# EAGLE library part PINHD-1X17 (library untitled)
PIN HEADER
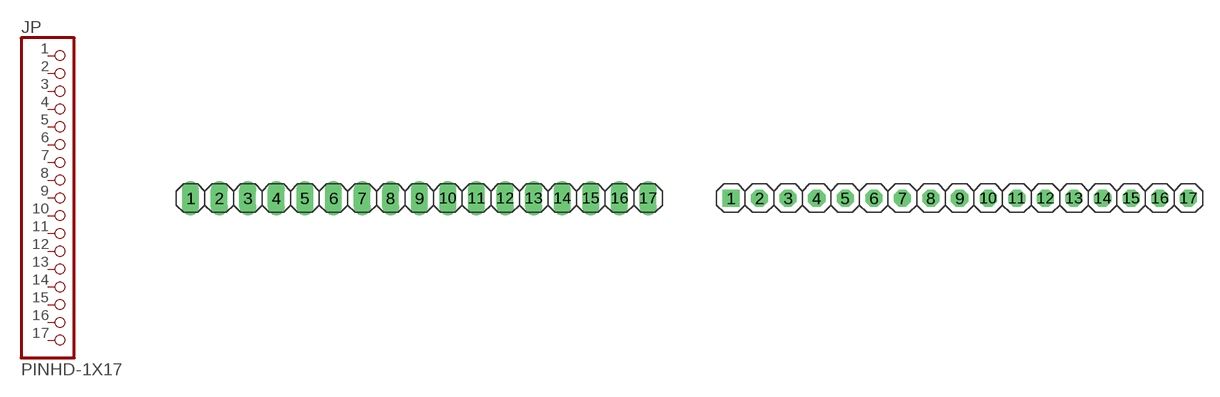
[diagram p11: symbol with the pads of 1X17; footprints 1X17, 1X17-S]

Designator prefix JP

## PINHD-1X17_2.54  [1X17]
1  1  pas
2  2  pas
3  3  pas
4  4  pas
5  5  pas
6  6  pas
7  7  pas
8  8  pas
9  9  pas
10  10  pas
11  11  pas
12  12  pas
13  13  pas
14  14  pas
15  15  pas
16  16  pas
17  17  pas

## PINHD-1X17_2.54-S  [1X17-S]
Pads as for 1X17

## PINHD-1X17_2.54-90°  [1X17/90]
Pads as for 1X17

## PINHD-1X17_2.54-90°-S  [1X17/90-S]
Pads as for 1X17

## PINHD-1X17_2.00  [1X17M]
Pads as for 1X17

## PINHD-1X17_2.54-SMD  [1X17SMD]
Pads as for 1X17

## PINHD-1X17_2.54-SMD-90°  [1X17SMD/90]
Pads as for 1X17

## Footprint 1X17 (pad centres in mm)
PIN HEADER - 2.54
drill 1.016 long: 1 -20.32,0; 2 -17.78,0; 3 -15.24,0; 4 -12.7,0; 5 -10.16,0; 6 -7.62,0; 7 -5.08,0; 8 -2.54,0; 9 0,0; 10 2.54,0; 11 5.08,0; 12 7.62,0; 13 10.16,0; 14 12.7,0; 15 15.24,0; 16 17.78,0; 17 20.32,0

## Footprint 1X17-S (pad centres in mm)
PIN HEADER - 2.54
drill 1.016 square: 1 -20.32,0
drill 1.016 octagon: 2 -17.78,0; 3 -15.24,0; 4 -12.7,0; 5 -10.16,0; 6 -7.62,0; 7 -5.08,0; 8 -2.54,0; 9 0,0; 10 2.54,0; 11 5.08,0; 12 7.62,0; 13 10.16,0; 14 12.7,0; 15 15.24,0; 16 17.78,0; 17 20.32,0

## Footprint 1X17/90 (pad centres in mm)
PIN HEADER - 2.54 90°
drill 1.016 long: 1 -20.32,-3.81; 2 -17.78,-3.81; 3 -15.24,-3.81; 4 -12.7,-3.81; 5 -10.16,-3.81; 6 -7.62,-3.81; 7 -5.08,-3.81; 8 -2.54,-3.81; 9 0,-3.81; 10 2.54,-3.81; 11 5.08,-3.81; 12 7.62,-3.81; 13 10.16,-3.81; 14 12.7,-3.81; 15 15.24,-3.81; 16 17.78,-3.81; 17 20.32,-3.81

## Footprint 1X17/90-S (pad centres in mm)
PIN HEADER - 2.54 90°
drill 1.016 square: 1 -20.32,-3.81
drill 1.016 octagon: 2 -17.78,-3.81; 3 -15.24,-3.81; 4 -12.7,-3.81; 5 -10.16,-3.81; 6 -7.62,-3.81; 7 -5.08,-3.81; 8 -2.54,-3.81; 9 0,-3.81; 10 2.54,-3.81; 11 5.08,-3.81; 12 7.62,-3.81; 13 10.16,-3.81; 14 12.7,-3.81; 15 15.24,-3.81; 16 17.78,-3.81; 17 20.32,-3.81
